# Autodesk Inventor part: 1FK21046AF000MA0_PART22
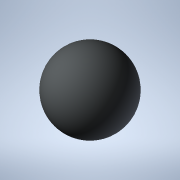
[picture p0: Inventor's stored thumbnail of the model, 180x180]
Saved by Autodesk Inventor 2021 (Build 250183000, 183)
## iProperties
Created: 2025-04
Part Number: 1FK21046AF000MA0_PART22
Material: Generic
Catalog Web Link: www.3dfindit.com
Description: -Servo synchronous motor
Document SubType Name: Modeling
Designer: psAdmin
Mass: 0.137258 g
Surface Area: 1.2868 cm^2
Volume: 0.137258 cm^3
Density: 1 g/cm^3
Appearance: PSOLRGB-212-217-219
Category: PARTsolutions
Title: 1FK21046AF000MA0_PART22
Author: Cadenas PARTsolutions
Comments: Servo synchronous motor
Sending System: PARTsolutions
Preprocessor: ST-DEVELOPER v19.3
PSOL_IDENT_0: {$CADENAS_DATA/23d-libs/siemens_ag/_cat_/1c/1f/1fk21046af000ma0.prj},216 {VTYP=3D},{NB=1FK21046AF000
PSOL_IDENT_1: MA0_PART22},{LINA=1FK21046AF000MA0_PART22},{NN=1FK21046AF000MA0_PART22},{NOPRJ=TRUE},{DATE=19.08.202
PSOL_IDENT_2: 5 14:00:28},{GEOMDATE=30.07.2025 02:02:08},{VERSION=},{LINEID=10},{WBVAR=},{WBNUMERIC=}  {NB=1FK2104
PSOL_IDENT_3: 6AF000MA0_PART22},{LINA=1FK21046AF000MA0_PART22},{KT=DUMMY},{PREVIEW=../../../_pool_/cb/72/p_d211_xx
PSOL_IDENT_4: _00434j.png},{DESCSHORT=SIMOTICS S-1FK2 HD, SINAMICS S210 3AC 400V-480V, 3.2 Nm, 3000 rpm},{DESCLONG=
PSOL_IDENT_5: SIMOTICS S-1FK2 HD servo motor M0=3.2 Nm; PN = 1 kW at nN=3000 rpm (380-480 V); PN = 0.5 kW at nN=15
PSOL_IDENT_6: 00 rpm (200-240 V); degree of protection IP64; cylindrical shaft D19x40mm; absolute encoder 22-bit +
PSOL_IDENT_7: 12-bit multiturn (encoder AM22DQC); with OCC interface; plug size M17, rotatable; SIMOTICS S-1FK2 s
PSOL_IDENT_8: ervomotorfor a wide range of uses in industrial environments. SIMOTICS S‑1FK2 servomotors are compac
PSOL_IDENT_9: t synchronous motors with a high dynamic performance that set themselves apart as a result of their
PSOL_IDENT_10: high power density, degree of protection and overload capability. The motors are available in two va
PSOL_IDENT_11: riants: as High Dynamic variant (highest dynamic performance as a result of the low intrinsic moment
PSOL_IDENT_12: of inertia for applications demanding a high dynamic performance with low moved masses) - and as Co
PSOL_IDENT_13: mpact variant (precise and stable closed-loop control for medium up to large moved masses as a resul
PSOL_IDENT_14: t of a medium intrinsic moment of inertia). SIMOTICSS‑1FK2 servomotors fully exploit their strengths
PSOL_IDENT_15: in a system with the SINAMICSS210 frequency converter and simple connection using the one cable con
PSOL_IDENT_16: nection (OCC). Advantages include the short control and positioning times, fast and precise correcti
PSOL_IDENT_17: on of disturbing quantities as well as stable control with a high dynamic performance. The servo mot
PSOL_IDENT_18: ors can be configured to address a wide range of requirements. For example with and without holding
PSOL_IDENT_19: brake, IP64 or IP65 degree of protection, singleturn or multiturn absolute encoders - to name just a
PSOL_IDENT_20: few. Further, the servomotors are available in different shaft heights extending from 20 to 100. A
PSOL_IDENT_21: shaft sealing ring is available to achieve an IP65 degree of protection and for subsequent mounting
PSOL_IDENT_22: at the motor or as spare part. SIMOTICS - the optimum motor for each and every motion control applic
PSOL_IDENT_23: ation.},{INTNO=195125049666},{SUPPLIERALTNO=1FK2104-6AF00-0MA0},{MANUID=1FK21046AF000MA0},{MANUNAME=
PSOL_IDENT_24: Siemens},{MANUTYPEDESC=Synchronous motor 1FK2-HD 3.2 NM},{AAU732=SIMOTICS},{AAO057=S-1FK2},{AAU734=S
PSOL_IDENT_25: IMOTICS S-1FK2 HD servo motor M0=3.2 Nm; PN = 1 kW at nN=3000 rpm (380-480 V); PN = 0.5 kW at nN=150
PSOL_IDENT_26: 0 rpm (200-240 V); degree of protection IP64; cylindrical shaft D19x40mm; absolute encoder 22-bit +
PSOL_IDENT_27: 12-bit multiturn (encoder AM22DQC); with OCC interface; plug size M17, rotatable;},{AAW338=Synchrono
PSOL_IDENT_28: us motor 1FK2-HD 3.2 NM},{AAO742=SIMOTICS},{AAO663=4042948694374},{NOCUPEROU=1},{PRICEQUANTITY=1},{Q
PSOL_IDENT_29: UANTITYMIN=1},{QUANTITYINT=1},{CTN=85015220},{COO=DE},{AAO676=1FK2104-6AF00-0MA0},{AAO677=Siemens AG
PSOL_IDENT_30: },{ORDERUNIT=C62},{CONTENTUNIT=C62}
NB: 1FK21046AF000MA0_PART22
NT: Servo synchronous motor
NBSYN: $MANUID._PART22
LINA: 1FK21046AF000MA0_PART22
CATALOG: SIEMENS
PREVIEW: ../../../_pool_/cb/72/p_d211_xx_00434j.png
DESCSHORT: SIMOTICS S-1FK2 HD, SINAMICS S210 3AC 400V-480V, 3.2 Nm, 3000 rpm
DESCLONG: SIMOTICS S-1FK2 HD servo motor M0=3.2 Nm; PN = 1 kW at nN=3000 rpm (380-480 V); PN = 0.5 kW at nN=1500 rpm (200-240 V); degree of protection IP64; cylindrical s
INTNO: 195125049666
SUPPLIERALTNO: 1FK2104-6AF00-0MA0
MANUID: 1FK21046AF000MA0
MANUNAME: Siemens
MANUTYPEDESC: Synchronous motor 1FK2-HD 3.2 NM
AAU732: SIMOTICS
AAO057: S-1FK2
AAU734: SIMOTICS S-1FK2 HD servo motor M0=3.2 Nm; PN = 1 kW at nN=3000 rpm (380-480 V); PN = 0.5 kW at nN=1500 rpm (200-240 V); degree of protection IP64; cylindrical s
AAW338: Synchronous motor 1FK2-HD 3.2 NM
AAO742: SIMOTICS
AAO663: 4042948694374.0
NOCUPEROU: 1
PRICEQUANTITY: 1
QUANTITYMIN: 1
QUANTITYINT: 1
CTN: 85015220
COO: DE
ARTICLENO: 1FK21046AF000MA0_PART22
BOMINFO: 1FK21046AF000MA0_PART22
CREATOR: CADENAS GmbH
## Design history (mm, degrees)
feature "2025_04_17_15_39_11_0412"
body "Solid1"
